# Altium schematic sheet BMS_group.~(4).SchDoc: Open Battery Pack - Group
size A3; Author: Morgane Vallée; Revision: 1.0; SheetNumber: 2; SheetTotal: 3
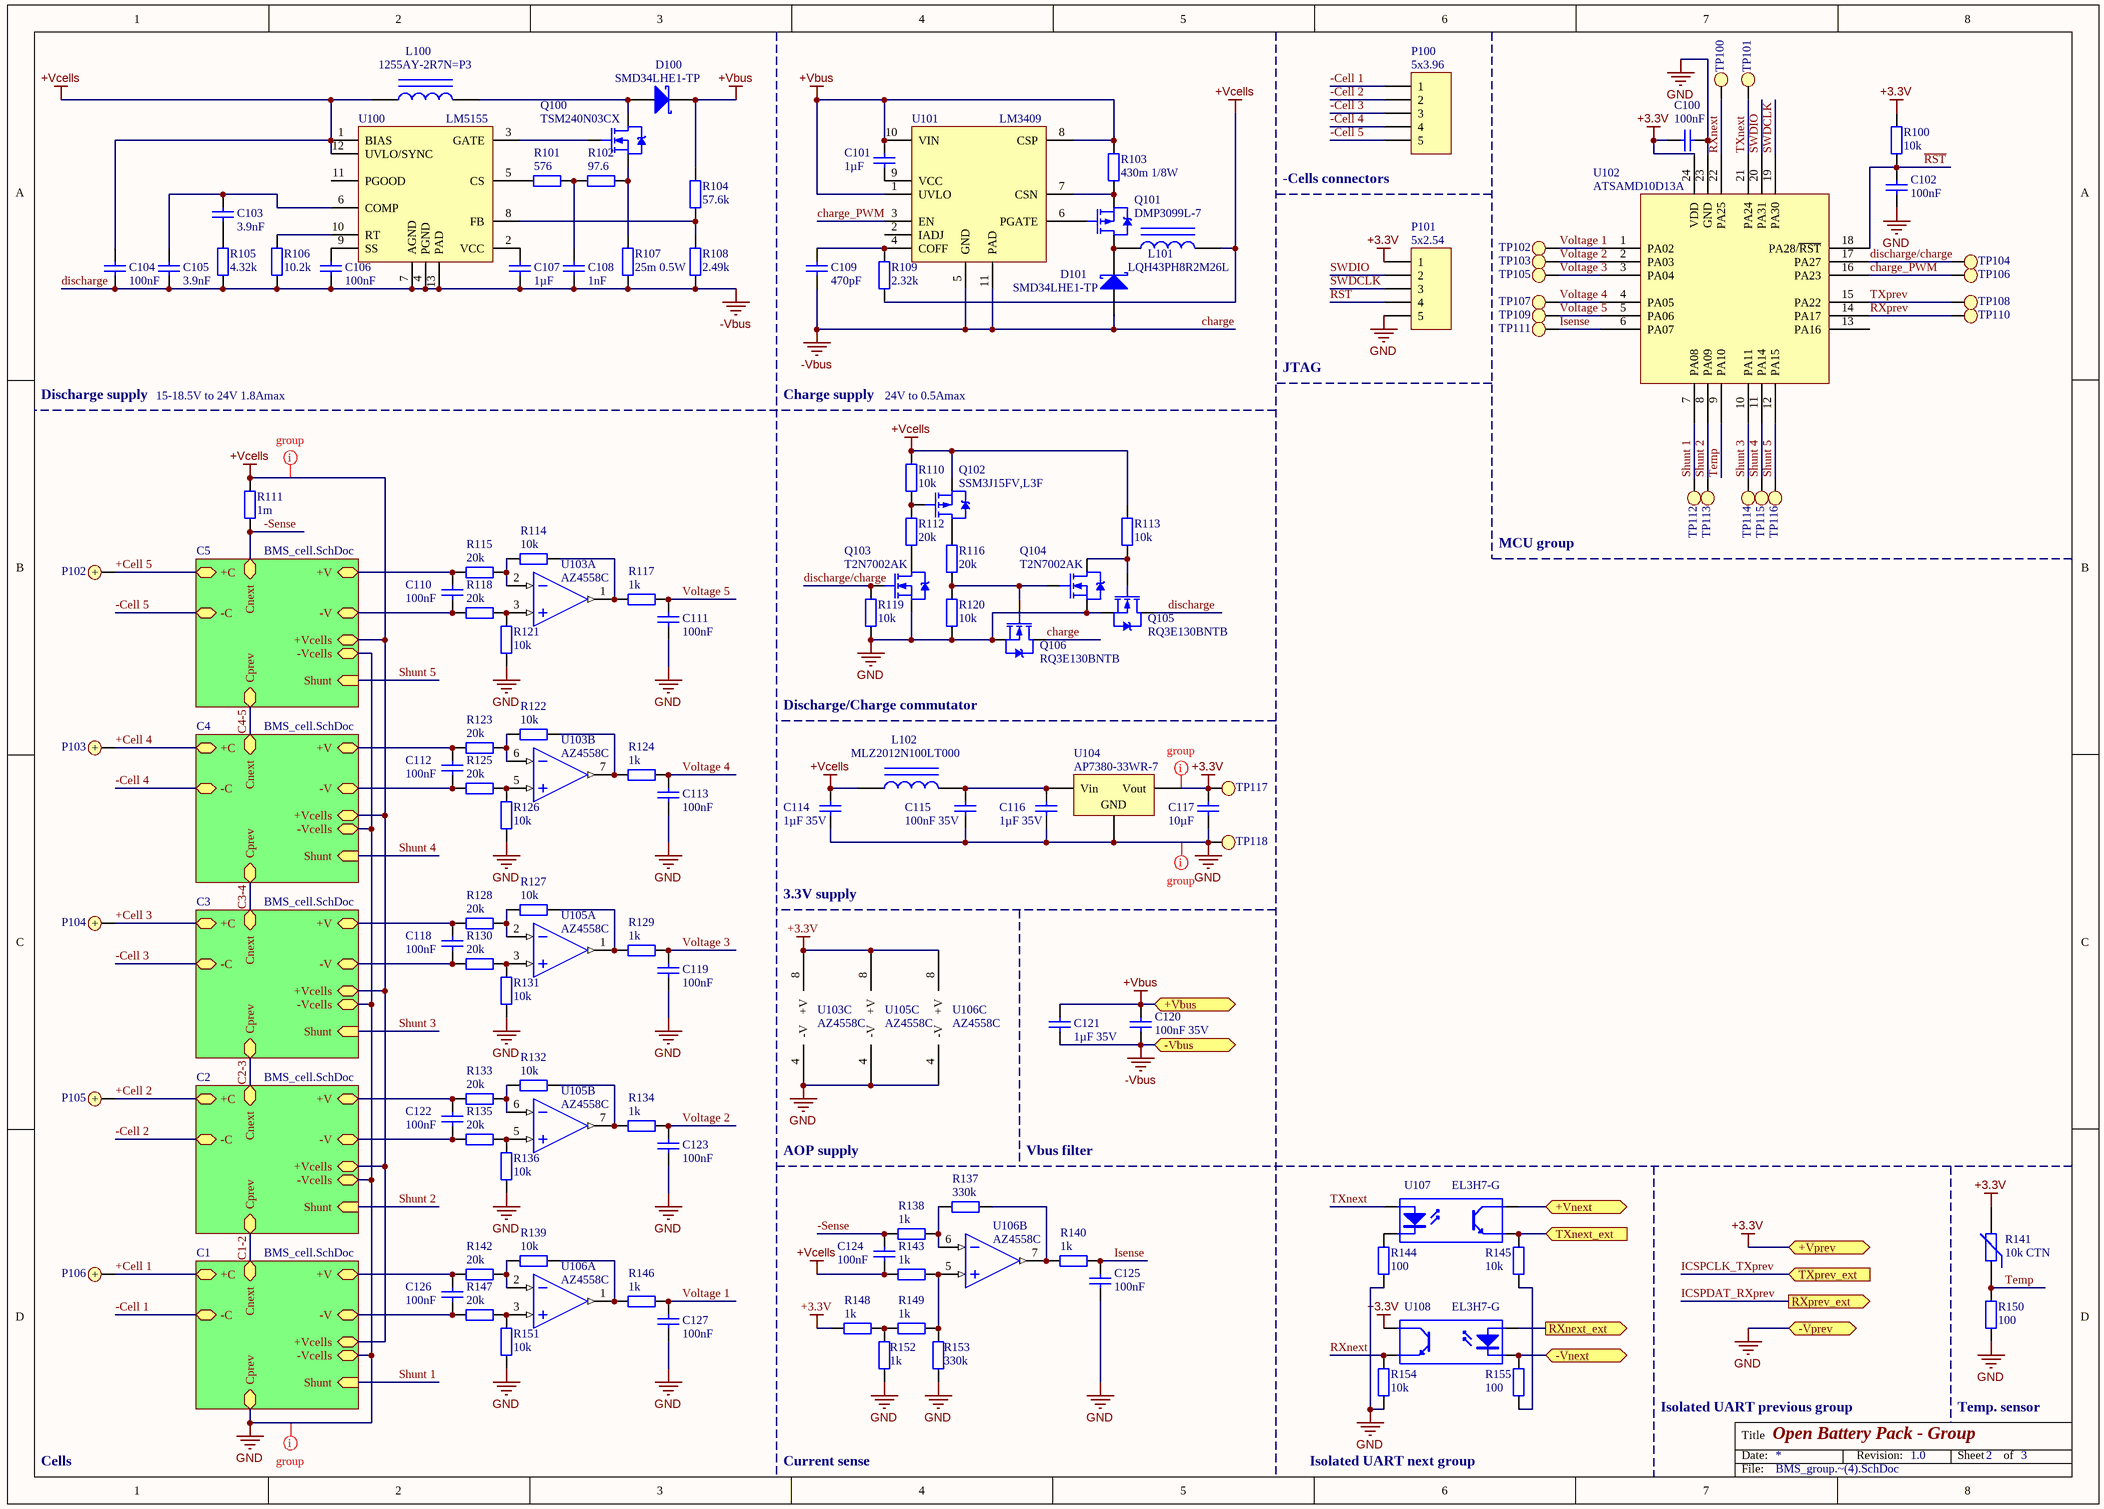
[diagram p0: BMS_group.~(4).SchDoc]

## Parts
C100  100nF  [C0603]
C101  1µF  [C0603]
C102  100nF  [C0603]
C103  3.9nF  [C0603]
C104  100nF  [C0603]
C105  3.9nF  [C0603]
C106  100nF  [C0603]
C107  1µF  [C0603]
C108  1nF  [C0603]
C109  470pF  [C0603]
C110  100nF  [C0603]
C111  100nF  [C0603]
C112  100nF  [C0603]
C113  100nF  [C0603]
C114  1µF 35V  [C0603]
C115  100nF 35V  [C0603]
C116  1µF 35V  [C0603]
C117  10µF  [C0603]
C118  100nF  [C0603]
C119  100nF  [C0603]
C120  100nF 35V  [C0603]
C121  1µF 35V  [C0603]
C122  100nF  [C0603]
C123  100nF  [C0603]
C124  100nF  [C0603]
C125  100nF  [C0603]
C126  100nF  [C0603]
C127  100nF  [C0603]
D100  SMD34LHE1-TP  [SOT-23_N]
D101  SMD34LHE1-TP  [SOT-23_N]
L100  1255AY-2R7N=P3  [AXIAL-0.9]
L101  LQH43PH8R2M26L  [AXIAL-0.9]
L102  MLZ2012N100LT000  [AXIAL-0.9]
P100  5x3.96  [HDR1X5]
P101  5x2.54  [HDR1X5]
P102  Bat+  [Keystone 241]  (value not drawn)
P103  Bat+  [Keystone 241]  (value not drawn)
P104  Bat+  [Keystone 241]  (value not drawn)
P105  Bat+  [Keystone 241]  (value not drawn)
P106  Bat+  [Keystone 241]  (value not drawn)
Q100  TSM240N03CX  [DIODES SOT-23-3]
Q101  DMP3099L-7  [DIODES SOT-23-3]
Q102  SSM3J15FV,L3F  [DIODES SOT-23-3]
Q103  T2N7002AK  [DIODES SOT-23-3]
Q104  T2N7002AK  [DIODES SOT-23-3]
Q105  RQ3E130BNTB  [DIODES SOT-23-3]
Q106  RQ3E130BNTB  [DIODES SOT-23-3]
R100  10k  [R0603]
R101  576  [R0603]
R102  97.6  [R0603]
R103  430m 1/8W  [R0603]
R104  57.6k  [R0603]
R105  4.32k  [R0603]
R106  10.2k  [R0603]
R107  25m 0.5W  [R0603]
R108  2.49k  [R0603]
R109  2.32k  [R0603]
R110  10k  [R0603]
R111  1m  [R0603]
R112  20k  [R0603]
R113  10k  [R0603]
R114  10k  [R0603]
R115  20k  [R0603]
R116  20k  [R0603]
R117  1k  [R0603]
R118  20k  [R0603]
R119  10k  [R0603]
R120  10k  [R0603]
R121  10k  [R0603]
R122  10k  [R0603]
R123  20k  [R0603]
R124  1k  [R0603]
R125  20k  [R0603]
R126  10k  [R0603]
R127  10k  [R0603]
R128  20k  [R0603]
R129  1k  [R0603]
R130  20k  [R0603]
R131  10k  [R0603]
R132  10k  [R0603]
R133  20k  [R0603]
R134  1k  [R0603]
R135  20k  [R0603]
R136  10k  [R0603]
R137  330k  [R0603]
R138  1k  [R0603]
R139  10k  [R0603]
R140  1k  [R0603]
R141  10k CTN  [NTC]
R142  20k  [R0603]
R143  1k  [R0603]
R144  100  [R0603]
R145  10k  [R0603]
R146  1k  [R0603]
R147  20k  [R0603]
R148  1k  [R0603]
R149  1k  [R0603]
R150  100  [R0603]
R151  10k  [R0603]
R152  1k  [R0603]
R153  330k  [R0603]
R154  10k  [R0603]
R155  100  [R0603]
TP100  Test Point  [Test Point]  (value not drawn)
TP101  Test Point  [Test Point]  (value not drawn)
TP102  Test Point  [Test Point]  (value not drawn)
TP103  Test Point  [Test Point]  (value not drawn)
TP104  Test Point  [Test Point]  (value not drawn)
TP105  Test Point  [Test Point]  (value not drawn)
TP106  Test Point  [Test Point]  (value not drawn)
TP107  Test Point  [Test Point]  (value not drawn)
TP108  Test Point  [Test Point]  (value not drawn)
TP109  Test Point  [Test Point]  (value not drawn)
TP110  Test Point  [Test Point]  (value not drawn)
TP111  Test Point  [Test Point]  (value not drawn)
TP112  Test Point  [Test Point]  (value not drawn)
TP113  Test Point  [Test Point]  (value not drawn)
TP114  Test Point  [Test Point]  (value not drawn)
TP115  Test Point  [Test Point]  (value not drawn)
TP116  Test Point  [Test Point]  (value not drawn)
TP117  Test Point  [Test Point]  (value not drawn)
TP118  Test Point  [Test Point]  (value not drawn)
U100  LM5155  [TI MSOP-10 DGQ]
U101  LM3409  [TI MSOP-10 DGQ]
U102  ATSAMD10D13A  [SMSC QFN-24 4x4MM]
U103  AZ4558C  [DIODES SO-8]  (parts A,B,C of 3)
U104  AP7380-33WR-7  [DIODES SOT-23-5 W5]
U105  AZ4558C  [DIODES SO-8]  (parts A,B,C of 3)
U106  AZ4558C  [DIODES SO-8]  (parts A,B,C of 3)
U107  EL3H7-G  [OPTO_EL3H7-G]
U108  EL3H7-G  [OPTO_EL3H7-G]

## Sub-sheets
C1 = BMS_cell.SchDoc: -C, -V, +C, +Vcells, Cnext, -Vcells, +V, Shunt (in), Cprev
C2 = BMS_cell.SchDoc: -C, -V, +C, +Vcells, Cnext, -Vcells, +V, Shunt (in), Cprev
C3 = BMS_cell.SchDoc: -C, -V, +C, +Vcells, Cnext, -Vcells, +V, Shunt (in), Cprev
C4 = BMS_cell.SchDoc: -C, -V, +C, +Vcells, Cnext, -Vcells, +V, Shunt (in), Cprev
C5 = BMS_cell.SchDoc: -C, -V, +C, +Vcells, Cnext, -Vcells, +V, Shunt (in), Cprev

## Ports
+Vbus, +Vnext, +Vprev, -Vbus, -Vnext, -Vprev, RXnext_ext (out), RXprev_ext (out), TXnext_ext (in), TXprev_ext (in)

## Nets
+3.3V: C100.2 C117.1 P101.1 R100.2 R141.2 R148.2 TP117.1 U102.24(VDD) U103.8(+V) U104.3(Vout) U105.8(+V) U106.8(+V) U108.4(C) ; port +Vprev
+Vbus: C101.1 C120.1 C121.1 D100.3(K) R103.2 R104.2 U101.1(UVLO) U101.8(CSP) U101.10(VIN) ; port +Vbus
+Vcells: C104.1 C114.1 C124.2 L100.1 L101.2 L102.1 Q102.2(S) R109.2 R110.2 R111.2 R113.2 R143.2 U100.1(BIAS) U100.12(UVLO/SYNC) ; sheet C1/+Vcells, sheet C2/+Vcells, sheet C3/+Vcells, sheet C4/+Vcells, sheet C5/+Vcells
charge: C104.2 C105.2 C106.2 C107.2 C108.2 C109.2 C120.2 C121.2 D101.1(A) Q105.3(D) Q106.3(D) R105.1 R106.1 R107.1 R108.1 U100.4(PGND) U100.7(AGND) U100.13(PAD) U101.5(GND) U101.11(PAD) ; port -Vbus  [also labelled -Vbus, discharge]
GND: C100.1 C102.1 C111.2 C113.2 C114.2 C115.2 C116.2 C117.2 C119.2 C123.2 C125.2 C127.2 P101.5 Q103.2(S) Q104.2(S) Q105.2(S) Q106.2(S) R119.1 R120.1 R121.2 R126.2 R131.2 R136.2 R144.1 R150.2 R151.2 R152.2 R153.1 R154.1 TP118.1 U102.23(GND) U103.4(-V) U104.2(GND) U105.4(-V) U106.4(-V) ; port -Vprev, sheet C1/-Vcells, sheet C1/Cprev, sheet C2/-Vcells, sheet C3/-Vcells, sheet C4/-Vcells, sheet C5/-Vcells
+Cell 1: P106.1 ; sheet C1/+C
+Cell 2: P105.1 ; sheet C2/+C
+Cell 3: P104.1 ; sheet C3/+C
+Cell 4: P103.1 ; sheet C4/+C
+Cell 5: P102.1 ; sheet C5/+C
+Vnext: U107.4(C) ; port +Vnext
-Cell 1: P100.1 ; sheet C1/-C
-Cell 2: P100.2 ; sheet C2/-C
-Cell 3: P100.3 ; sheet C3/-C
-Cell 4: P100.4 ; sheet C4/-C
-Cell 5: P100.5 ; sheet C5/-C
-Sense: C124.1 R111.1 R138.1 ; sheet C5/Cnext
-Vnext: R155.1 U108.2(K) ; port -Vnext
C1-2: sheet C1/Cnext, sheet C2/Cprev
C2-3: sheet C2/Cnext, sheet C3/Cprev
C3-4: sheet C3/Cnext, sheet C4/Cprev
C4-5: sheet C4/Cnext, sheet C5/Cprev
charge_PWM: TP106.1 U101.3(EN) U102.16(PA23)
discharge/charge: Q103.1(G) R119.2 TP104.1 U102.17(PA27)
Isense: C125.1 R140.1 TP111.1 U102.6(PA07)
~{RST}: C102.2 P101.4 R100.1 U102.18(PA28/~{RST})
RXnext: R154.2 TP100.1 U102.22(PA25) U108.3(E)
RXnext_ext: U108.1(A) ; port RXnext_ext
RXprev: TP110.1 U102.14(PA17)
Shunt 1: TP112.1 U102.7(PA08) ; sheet C1/Shunt
Shunt 2: TP113.1 U102.8(PA09) ; sheet C2/Shunt
Shunt 3: TP114.1 U102.10(PA11) ; sheet C3/Shunt
Shunt 4: TP115.1 U102.11(PA14) ; sheet C4/Shunt
Shunt 5: TP116.1 U102.12(PA15) ; sheet C5/Shunt
SWDCLK: P101.3 U102.19(PA30)
SWDIO: P101.2 U102.20(PA31)
Temp: R141.1 R150.1 U102.9(PA10)
TXnext: TP101.1 U102.21(PA24) U107.1(A)
TXnext_ext: R145.1 U107.3(E) ; port TXnext_ext
TXprev: TP108.1 U102.15(PA22)
Voltage 1: C127.1 R146.1 TP102.1 U102.1(PA02)
Voltage 2: C123.1 R134.1 TP103.1 U102.2(PA03)
Voltage 3: C119.1 R129.1 TP105.1 U102.3(PA04)
Voltage 4: C113.1 R124.1 TP107.1 U102.4(PA05)
Voltage 5: C111.1 R117.1 TP109.1 U102.5(PA06)
NetC101_2: C101.2 U101.9(VCC)
NetC103_1: C103.1 C105.1 U100.6(COMP)
NetC103_2: C103.2 R105.2
NetC106_1: C106.1 U100.9(SS)
NetC107_1: C107.1 U100.2(VCC)
NetC108_1: C108.1 R101.1 R102.2
NetC109_1: C109.1 R109.1 U101.4(COFF)
NetC110_1: C110.1 R115.1 ; sheet C5/+V
NetC110_2: C110.2 R118.2 ; sheet C5/-V
NetC112_1: C112.1 R123.1 ; sheet C4/+V
NetC112_2: C112.2 R125.2 ; sheet C4/-V
NetC115_1: C115.1 C116.1 L102.2 U104.1(Vin)
NetC118_1: C118.1 R128.1 ; sheet C3/+V
NetC118_2: C118.2 R130.2 ; sheet C3/-V
NetC122_1: C122.1 R133.1 ; sheet C2/+V
NetC122_2: C122.2 R135.2 ; sheet C2/-V
NetC126_1: C126.1 R142.1 ; sheet C1/+V
NetC126_2: C126.2 R147.2 ; sheet C1/-V
NetD100_1: D100.1(A) L100.2 Q100.3(D)
NetD101_3: D101.3(K) L101.1 Q101.3(D)
NetQ100_1: Q100.1(G) U100.3(GATE)
NetQ100_2: Q100.2(S) R102.1 R107.2
NetQ101_1: Q101.1(G) U101.6(PGATE)
NetQ101_2: Q101.2(S) R103.1 U101.7(CSN)
NetQ102_1: Q102.1(G) R110.1 R112.2
NetQ102_3: Q102.3(D) R116.2
NetQ103_3: Q103.3(D) R112.1
NetQ104_1: Q104.1(G) Q106.1(G) R116.1 R120.2
NetQ104_3: Q104.3(D) Q105.1(G) R113.1
NetR101_2: R101.2 U100.5(CS)
NetR104_1: R104.1 R108.2 U100.8(FB)
NetR106_2: R106.2 U100.10(RT)
NetR114_1: R114.1 R115.2 U103.2(IN-)
NetR114_2: R114.2 R117.2 U103.1(OUT)
NetR118_1: R118.1 R121.1 U103.3(IN+)
NetR122_1: R122.1 R123.2 U103.6(IN-)
NetR122_2: R122.2 R124.2 U103.7(OUT)
NetR125_1: R125.1 R126.1 U103.5(IN+)
NetR127_1: R127.1 R128.2 U105.2(IN-)
NetR127_2: R127.2 R129.2 U105.1(OUT)
NetR130_1: R130.1 R131.1 U105.3(IN+)
NetR132_1: R132.1 R133.2 U105.6(IN-)
NetR132_2: R132.2 R134.2 U105.7(OUT)
NetR135_1: R135.1 R136.1 U105.5(IN+)
NetR137_1: R137.1 R140.2 U106.7(OUT)
NetR137_2: R137.2 R138.2 U106.6(IN-)
NetR139_1: R139.1 R142.2 U106.2(IN-)
NetR139_2: R139.2 R146.2 U106.1(OUT)
NetR143_1: R143.1 R149.1 R153.2 U106.5(IN+)
NetR144_2: R144.2 U107.2(K)
NetR145_2: R145.2 R155.2
NetR147_1: R147.1 R151.1 U106.3(IN+)
NetR148_1: R148.1 R149.2 R152.1

Not connected (* = marked no-connect by the designer): U100 11(PGOOD); U101 2(IADJ); U102 13(PA16)

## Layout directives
net class Group: +3.3V, +Vcells, GND

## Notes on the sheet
- (near P100) -Cells connectors
- JTAG
- Discharge supply
- 15-18.5V to 24V 1.8Amax
- Charge supply
- 24V to 0.5Amax
- MCU group
- Discharge/Charge commutator
- 3.3V supply
- AOP supply
- Vbus filter
- Isolated UART previous group
- Temp. sensor
- Cells
- Current sense
- Isolated UART next group

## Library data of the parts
C100-C127 = Cap: Capacitor
D100 D101 = Diode BAT17
L100-L102 = Inductor Iron: Magnetic-Core Inductor
P100 P101 = Header 5: Header, 5-Pin
P102-P106 = Bat+: Battery contact +
Q100 Q103-Q106 = MOSFET_N
Q101 Q102 = MOSFET_P
R100-R140 R142-R155 = Res2: Resistor
R141 = Res Varistor: Varistor (Voltage-Sensitive Resistor)
U100 = LM5155: 2.2-MHz Wide Input Nonsynchronous Boost, SEPIC, Flyback Controller
U101 = LM3409: P-FET Buck Controller for High-Power LED Drivers
U103 U105 U106 = LM2904: Low-power dual operational amplifiers
U104 = Volt Reg: Voltage Regulator
U107 U108 = Optoisolator1: 4-Pin Phototransistor Optocoupler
